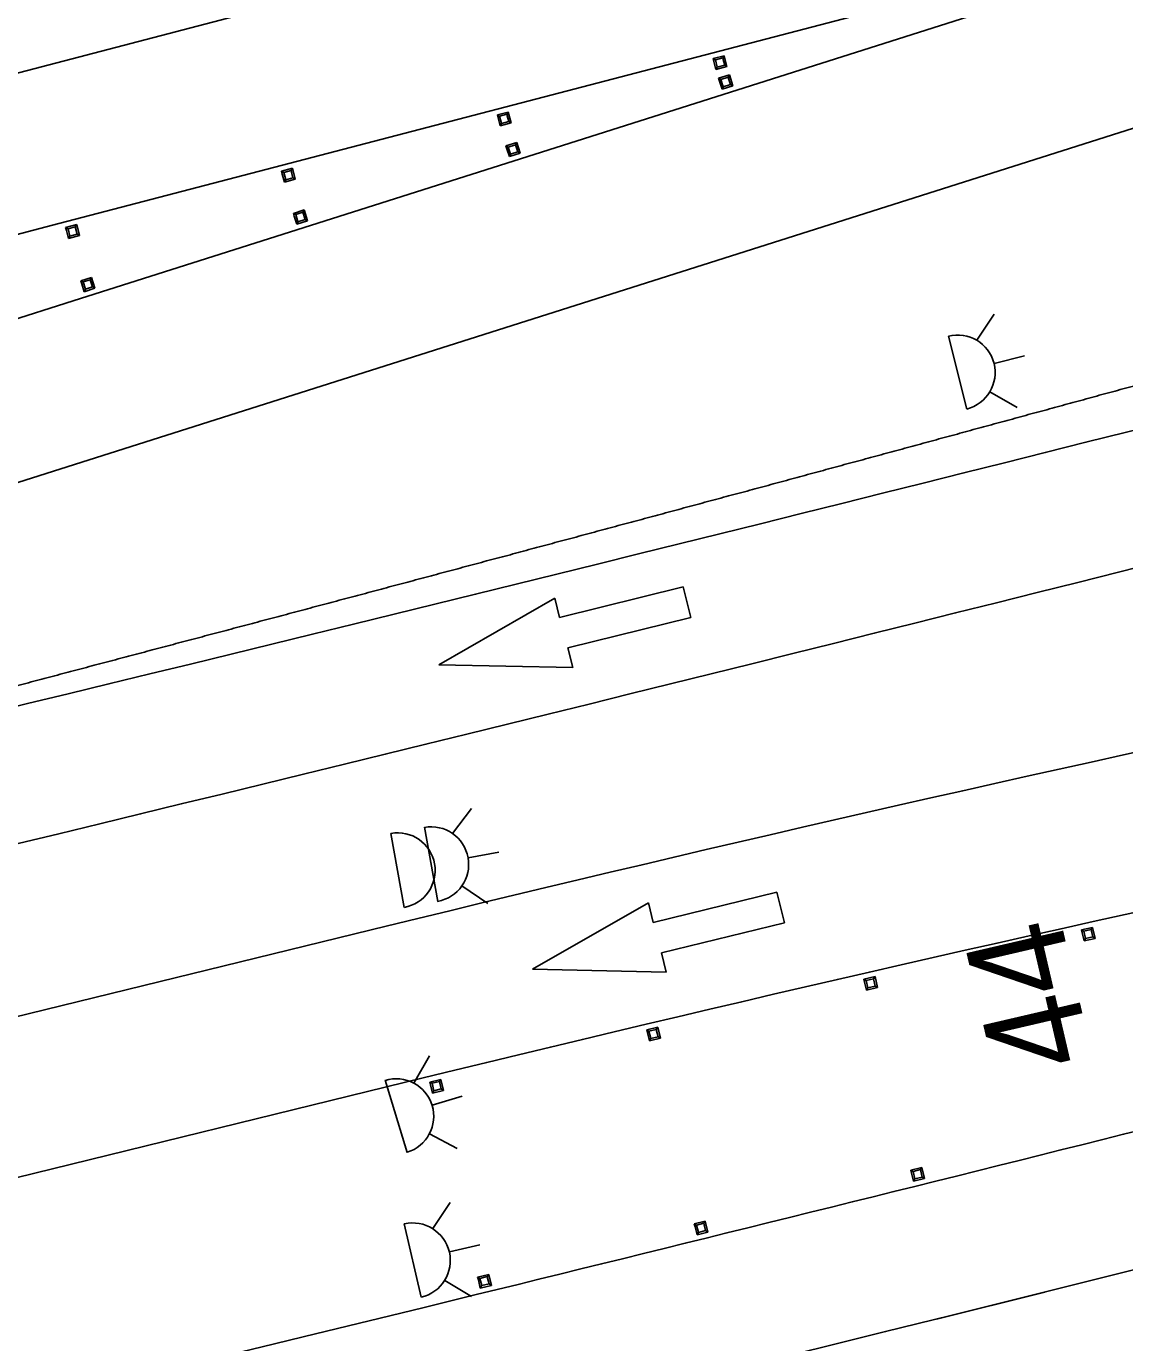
# Model space of a CAD drawing. Extents: x 2471014 to 2497726, y 6959577 to 6980268.
# Drawn here: x 2483642.2 to 2483740.7, y 6967742.6 to 6967860.6 of the extents above; entities that cross this region are included whole.
import ezdxf

# ---------------------------------------------------------------- set-up
doc = ezdxf.new("R2010")
doc.units = 0
for name, color, linetype in [('1', 7, 'Continuous'), ('13', 7, 'Continuous'), ('18', 7, 'Continuous'), ('23', 7, 'Continuous'), ('25', 7, 'Continuous'), ('5', 7, 'Continuous'), ('ALIGN_ML_IH35_NB_SB', 7, 'Continuous'), ('C-COMM-IDEN', 7, 'Continuous'), ('Level 30', 7, 'Continuous'), ('PMK_Del_D-SY_SZ_TYC_CTB', 7, 'Continuous'), ('PMK_Pav_Mark_Wht_Number', 7, 'Continuous'), ('S-BRDG-DECK', 7, 'Continuous'), ('V7_25', 7, 'Continuous')]:
    doc.layers.add(name, color=color, linetype=linetype)

msp = doc.modelspace()

# ---------------------------------------------------------------- linework, layer by layer
at = {"layer": '1'}
msp.add_line((2483733.49, 6967747.11), (2483723.78, 6967744.69), dxfattribs=at)
at = {"layer": '13'}
for p, q in [((2483621.13, 6967813.26), (2483744.66, 6967852.49)), ((2483645.1, 6967842.9), (2483440.68, 6967789.54)), ((2483529.53, 6967730.02), (2483677.76, 6967766.3))]:
    msp.add_line(p, q, dxfattribs=at)
msp.add_arc((2480976.22, 6978803.49), 11334, 283.600619, 284.818275, dxfattribs=at)
at = {"layer": '18'}
for p, q in [((2483589.04, 6967842.74), (2483885.7, 6967920.19)), ((2483453.46, 6967774.7), (2483647.04, 6967836.18)), ((2483526.2, 6967743.62), (2483674.43, 6967779.9))]:
    msp.add_line(p, q, dxfattribs=at)
for centre, radius, start, end in [((2484355.58, 6964997.05), 2865, 99.97631, 103.75383), ((2480975.49, 6978806.4), 11386, 280.569873, 283.75381)]:
    msp.add_arc(centre, radius, start, end, dxfattribs=at)
for points in [[(2483785.94, 6967840.59), (2483785, 6967840.33), (2483784.06, 6967840.07), (2483783.12, 6967839.81), (2483782.17, 6967839.55), (2483781.23, 6967839.29), (2483780.29, 6967839.03), (2483779.35, 6967838.77), (2483778.41, 6967838.51), (2483777.47, 6967838.25), (2483776.53, 6967837.98), (2483775.58, 6967837.72), (2483774.64, 6967837.46), (2483773.7, 6967837.2), (2483772.76, 6967836.94), (2483771.82, 6967836.68), (2483770.88, 6967836.42), (2483769.94, 6967836.16), (2483768.99, 6967835.9), (2483768.05, 6967835.64), (2483767.11, 6967835.38), (2483766.17, 6967835.12), (2483765.23, 6967834.86), (2483764.29, 6967834.6), (2483763.34, 6967834.35), (2483762.4, 6967834.09), (2483761.46, 6967833.83), (2483760.52, 6967833.57), (2483759.58, 6967833.31), (2483758.63, 6967833.05), (2483757.69, 6967832.79), (2483756.75, 6967832.53), (2483755.81, 6967832.27), (2483754.87, 6967832.01), (2483753.92, 6967831.75), (2483752.98, 6967831.5), (2483752.04, 6967831.24), (2483751.1, 6967830.98), (2483750.16, 6967830.72), (2483749.21, 6967830.46), (2483748.27, 6967830.2), (2483747.33, 6967829.95), (2483746.39, 6967829.69), (2483745.45, 6967829.43), (2483744.5, 6967829.17), (2483743.56, 6967828.91), (2483742.62, 6967828.66), (2483741.68, 6967828.4), (2483740.73, 6967828.14), (2483739.79, 6967827.88), (2483738.85, 6967827.63), (2483737.91, 6967827.37), (2483736.97, 6967827.11), (2483736.02, 6967826.86), (2483735.08, 6967826.6), (2483734.14, 6967826.34), (2483733.2, 6967826.08), (2483732.25, 6967825.83), (2483731.31, 6967825.57), (2483730.37, 6967825.31), (2483729.42, 6967825.06), (2483728.48, 6967824.8), (2483727.54, 6967824.55), (2483726.6, 6967824.29), (2483725.65, 6967824.03), (2483724.71, 6967823.78), (2483723.77, 6967823.52), (2483722.83, 6967823.26), (2483721.88, 6967823.01), (2483720.94, 6967822.75), (2483720, 6967822.5), (2483719.05, 6967822.24), (2483718.11, 6967821.99), (2483717.17, 6967821.73), (2483716.23, 6967821.47)], [(2483716.23, 6967821.47), (2483715.28, 6967821.22), (2483714.34, 6967820.96), (2483713.4, 6967820.71), (2483712.45, 6967820.45), (2483711.51, 6967820.2), (2483710.57, 6967819.94), (2483709.62, 6967819.69), (2483708.68, 6967819.43), (2483707.74, 6967819.18), (2483706.8, 6967818.92), (2483705.85, 6967818.67), (2483704.91, 6967818.42), (2483703.97, 6967818.16), (2483703.02, 6967817.91), (2483702.08, 6967817.65), (2483701.14, 6967817.4), (2483700.19, 6967817.14), (2483699.25, 6967816.89), (2483698.31, 6967816.64), (2483697.36, 6967816.38), (2483696.42, 6967816.13), (2483695.48, 6967815.88), (2483694.53, 6967815.62), (2483693.59, 6967815.37), (2483692.64, 6967815.12), (2483691.7, 6967814.86), (2483690.76, 6967814.61), (2483689.81, 6967814.36), (2483688.87, 6967814.1), (2483687.93, 6967813.85), (2483686.98, 6967813.6), (2483686.04, 6967813.34), (2483685.1, 6967813.09), (2483684.15, 6967812.84), (2483683.21, 6967812.59), (2483682.26, 6967812.33), (2483681.32, 6967812.08), (2483680.38, 6967811.83), (2483679.43, 6967811.58), (2483678.49, 6967811.32), (2483677.55, 6967811.07), (2483676.6, 6967810.82), (2483675.66, 6967810.57), (2483674.71, 6967810.32), (2483673.77, 6967810.06), (2483672.83, 6967809.81), (2483671.88, 6967809.56), (2483670.94, 6967809.31), (2483669.99, 6967809.06), (2483669.05, 6967808.81), (2483668.11, 6967808.56), (2483667.16, 6967808.3), (2483666.22, 6967808.05), (2483665.27, 6967807.8), (2483664.33, 6967807.55), (2483663.38, 6967807.3), (2483662.44, 6967807.05), (2483661.5, 6967806.8), (2483660.55, 6967806.55), (2483659.61, 6967806.3), (2483658.66, 6967806.05), (2483657.72, 6967805.8), (2483656.77, 6967805.55), (2483655.83, 6967805.3), (2483654.88, 6967805.05), (2483653.94, 6967804.8), (2483653, 6967804.55), (2483652.05, 6967804.3), (2483651.11, 6967804.05), (2483650.16, 6967803.8), (2483649.22, 6967803.55), (2483648.27, 6967803.3), (2483647.33, 6967803.05), (2483646.38, 6967802.8)], [(2483646.38, 6967802.8), (2483645.44, 6967802.55), (2483644.49, 6967802.3), (2483643.55, 6967802.05), (2483642.6, 6967801.8), (2483641.66, 6967801.55), (2483640.72, 6967801.3), (2483639.77, 6967801.05), (2483638.83, 6967800.81), (2483637.88, 6967800.56), (2483636.94, 6967800.31), (2483635.99, 6967800.06), (2483635.05, 6967799.81), (2483634.1, 6967799.56), (2483633.16, 6967799.31), (2483632.21, 6967799.07), (2483631.27, 6967798.82), (2483630.32, 6967798.57), (2483629.38, 6967798.32), (2483628.43, 6967798.07), (2483627.49, 6967797.83), (2483626.54, 6967797.58), (2483625.6, 6967797.33), (2483624.65, 6967797.08), (2483623.7, 6967796.84), (2483622.76, 6967796.59), (2483621.81, 6967796.34), (2483620.87, 6967796.09), (2483619.92, 6967795.85), (2483618.98, 6967795.6), (2483618.03, 6967795.35), (2483617.09, 6967795.11), (2483616.14, 6967794.86), (2483615.2, 6967794.61), (2483614.25, 6967794.37), (2483613.31, 6967794.12), (2483612.36, 6967793.87), (2483611.41, 6967793.63), (2483610.47, 6967793.38), (2483609.52, 6967793.13), (2483608.58, 6967792.89), (2483607.63, 6967792.64), (2483606.69, 6967792.4), (2483605.74, 6967792.15), (2483604.8, 6967791.9), (2483603.85, 6967791.66), (2483602.9, 6967791.41), (2483601.96, 6967791.17), (2483601.01, 6967790.92), (2483600.07, 6967790.68), (2483599.12, 6967790.43), (2483598.17, 6967790.19), (2483597.23, 6967789.94), (2483596.28, 6967789.69), (2483595.34, 6967789.45), (2483594.39, 6967789.2), (2483593.45, 6967788.96), (2483592.5, 6967788.72), (2483591.55, 6967788.47), (2483590.61, 6967788.23), (2483589.66, 6967787.98), (2483588.72, 6967787.74), (2483587.77, 6967787.49), (2483586.82, 6967787.25), (2483585.88, 6967787), (2483584.93, 6967786.76), (2483583.98, 6967786.52), (2483583.04, 6967786.27), (2483582.09, 6967786.03), (2483581.15, 6967785.78), (2483580.2, 6967785.54), (2483579.25, 6967785.3), (2483578.31, 6967785.05), (2483577.36, 6967784.81), (2483576.41, 6967784.57)]]:
    msp.add_spline(points, degree=3, dxfattribs=at)
at = {"layer": '23'}
for p, q in [((2483703.76, 6967857.7), (2483704.74, 6967857.95)), ((2483704.74, 6967857.95), (2483704.62, 6967857.76)), ((2483704.99, 6967856.97), (2483704.74, 6967857.95)), ((2483703.96, 6967857.59), (2483703.76, 6967857.7)), ((2483703.76, 6967857.7), (2483703.83, 6967857.44)), ((2483703.83, 6967857.44), (2483704.01, 6967856.72)), ((2483704.13, 6967856.93), (2483703.96, 6967857.59)), ((2483704.99, 6967856.97), (2483704.01, 6967856.72)), ((2483704.01, 6967856.72), (2483704.13, 6967856.93)), ((2483704.62, 6967857.76), (2483704.65, 6967857.62)), ((2483704.65, 6967857.62), (2483704.79, 6967857.1)), ((2483704.79, 6967857.1), (2483704.99, 6967856.97)), ((2483704.24, 6967855.92), (2483705.21, 6967856.23)), ((2483704.45, 6967855.82), (2483704.24, 6967855.92)), ((2483704.24, 6967855.92), (2483704.33, 6967855.66)), ((2483704.33, 6967855.66), (2483704.55, 6967854.95)), ((2483704.66, 6967855.17), (2483704.45, 6967855.82)), ((2483705.21, 6967856.23), (2483705.1, 6967856.02)), ((2483705.1, 6967856.02), (2483705.14, 6967855.89)), ((2483705.14, 6967855.89), (2483705.3, 6967855.38)), ((2483705.52, 6967855.26), (2483705.21, 6967856.23)), ((2483705.52, 6967855.26), (2483704.55, 6967854.95)), ((2483704.55, 6967854.95), (2483704.66, 6967855.17)), ((2483705.3, 6967855.38), (2483705.52, 6967855.26)), ((2483684.41, 6967852.65), (2483685.39, 6967852.9)), ((2483684.61, 6967852.53), (2483684.41, 6967852.65)), ((2483684.41, 6967852.65), (2483684.47, 6967852.39)), ((2483684.47, 6967852.39), (2483684.66, 6967851.66)), ((2483684.78, 6967851.88), (2483684.61, 6967852.53)), ((2483685.39, 6967852.9), (2483685.26, 6967852.7)), ((2483685.26, 6967852.7), (2483685.3, 6967852.57)), ((2483685.3, 6967852.57), (2483685.43, 6967852.05)), ((2483685.64, 6967851.92), (2483685.39, 6967852.9)), ((2483685.43, 6967852.05), (2483685.64, 6967851.92)), ((2483685.64, 6967851.92), (2483684.66, 6967851.66)), ((2483684.66, 6967851.66), (2483684.78, 6967851.88)), ((2483685.18, 6967849.86), (2483686.15, 6967850.17)), ((2483685.39, 6967849.76), (2483685.18, 6967849.86)), ((2483685.18, 6967849.86), (2483685.26, 6967849.61)), ((2483685.26, 6967849.61), (2483685.49, 6967848.9)), ((2483685.6, 6967849.12), (2483685.39, 6967849.76)), ((2483686.15, 6967850.17), (2483686.04, 6967849.97)), ((2483686.04, 6967849.97), (2483686.08, 6967849.83)), ((2483686.08, 6967849.83), (2483686.24, 6967849.32)), ((2483686.46, 6967849.2), (2483686.15, 6967850.17)), ((2483686.46, 6967849.2), (2483685.49, 6967848.9)), ((2483685.49, 6967848.9), (2483685.6, 6967849.12)), ((2483686.24, 6967849.32), (2483686.46, 6967849.2)), ((2483665.05, 6967847.59), (2483666.04, 6967847.85)), ((2483665.26, 6967847.48), (2483665.05, 6967847.59)), ((2483665.05, 6967847.59), (2483665.12, 6967847.33)), ((2483665.12, 6967847.33), (2483665.31, 6967846.61)), ((2483665.43, 6967846.83), (2483665.26, 6967847.48)), ((2483666.04, 6967847.85), (2483665.91, 6967847.65)), ((2483665.91, 6967847.65), (2483665.95, 6967847.52)), ((2483665.95, 6967847.52), (2483666.08, 6967847)), ((2483666.29, 6967846.87), (2483666.04, 6967847.85)), ((2483666.29, 6967846.87), (2483665.31, 6967846.61)), ((2483665.31, 6967846.61), (2483665.43, 6967846.83)), ((2483666.08, 6967847), (2483666.29, 6967846.87)), ((2483666.12, 6967843.81), (2483667.09, 6967844.12)), ((2483666.33, 6967843.71), (2483666.12, 6967843.81)), ((2483666.12, 6967843.81), (2483666.2, 6967843.55)), ((2483666.53, 6967843.06), (2483666.33, 6967843.71)), ((2483667.09, 6967844.12), (2483666.97, 6967843.91)), ((2483666.97, 6967843.91), (2483667.02, 6967843.78)), ((2483667.02, 6967843.78), (2483667.18, 6967843.27)), ((2483667.39, 6967843.15), (2483667.09, 6967844.12)), ((2483645.7, 6967842.54), (2483646.69, 6967842.8)), ((2483645.91, 6967842.43), (2483645.7, 6967842.54)), ((2483645.7, 6967842.54), (2483645.77, 6967842.28)), ((2483646.69, 6967842.8), (2483646.56, 6967842.6)), ((2483646.56, 6967842.6), (2483646.6, 6967842.46)), ((2483646.94, 6967841.82), (2483646.69, 6967842.8)), ((2483666.2, 6967843.55), (2483666.43, 6967842.84)), ((2483667.39, 6967843.15), (2483666.43, 6967842.84)), ((2483666.43, 6967842.84), (2483666.53, 6967843.06)), ((2483667.18, 6967843.27), (2483667.39, 6967843.15)), ((2483645.77, 6967842.28), (2483645.96, 6967841.56)), ((2483646.08, 6967841.77), (2483645.91, 6967842.43)), ((2483646.94, 6967841.82), (2483645.96, 6967841.56)), ((2483645.96, 6967841.56), (2483646.08, 6967841.77)), ((2483646.6, 6967842.46), (2483646.73, 6967841.95)), ((2483646.73, 6967841.95), (2483646.94, 6967841.82)), ((2483647.06, 6967837.76), (2483648.03, 6967838.06)), ((2483648.03, 6967838.06), (2483647.91, 6967837.86)), ((2483647.91, 6967837.86), (2483647.96, 6967837.73)), ((2483648.33, 6967837.1), (2483648.03, 6967838.06)), ((2483647.27, 6967837.66), (2483647.06, 6967837.76)), ((2483647.06, 6967837.76), (2483647.14, 6967837.5)), ((2483647.14, 6967837.5), (2483647.37, 6967836.79)), ((2483647.47, 6967837.01), (2483647.27, 6967837.66)), ((2483648.33, 6967837.1), (2483647.37, 6967836.79)), ((2483647.37, 6967836.79), (2483647.47, 6967837.01)), ((2483647.96, 6967837.73), (2483648.12, 6967837.22)), ((2483648.12, 6967837.22), (2483648.33, 6967837.1)), ((2483736.79, 6967779.57), (2483737.78, 6967779.79)), ((2483736.99, 6967779.45), (2483736.79, 6967779.57)), ((2483736.79, 6967779.57), (2483736.85, 6967779.31)), ((2483736.85, 6967779.31), (2483737.01, 6967778.58)), ((2483737.14, 6967778.79), (2483736.99, 6967779.45)), ((2483738, 6967778.8), (2483737.01, 6967778.58)), ((2483737.01, 6967778.58), (2483737.14, 6967778.79)), ((2483737.78, 6967779.79), (2483737.65, 6967779.6)), ((2483737.65, 6967779.6), (2483737.68, 6967779.46)), ((2483737.68, 6967779.46), (2483737.8, 6967778.94)), ((2483738, 6967778.8), (2483737.78, 6967779.79)), ((2483737.8, 6967778.94), (2483738, 6967778.8)), ((2483717.28, 6967775.16), (2483718.27, 6967775.39)), ((2483718.27, 6967775.39), (2483718.14, 6967775.2)), ((2483718.5, 6967774.4), (2483718.27, 6967775.39)), ((2483717.48, 6967775.04), (2483717.28, 6967775.16)), ((2483717.28, 6967775.16), (2483717.34, 6967774.9)), ((2483717.34, 6967774.9), (2483717.51, 6967774.17)), ((2483717.63, 6967774.38), (2483717.48, 6967775.04)), ((2483718.5, 6967774.4), (2483717.51, 6967774.17)), ((2483717.51, 6967774.17), (2483717.63, 6967774.38)), ((2483718.14, 6967775.2), (2483718.17, 6967775.06)), ((2483718.17, 6967775.06), (2483718.29, 6967774.54)), ((2483718.29, 6967774.54), (2483718.5, 6967774.4)), ((2483697.8, 6967770.61), (2483698.79, 6967770.85)), ((2483698, 6967770.5), (2483697.8, 6967770.61)), ((2483697.8, 6967770.61), (2483697.86, 6967770.35)), ((2483698.79, 6967770.85), (2483698.66, 6967770.65)), ((2483698.66, 6967770.65), (2483698.69, 6967770.52)), ((2483698.69, 6967770.52), (2483698.82, 6967770)), ((2483699.02, 6967769.86), (2483698.79, 6967770.85)), ((2483697.86, 6967770.35), (2483698.04, 6967769.63)), ((2483698.16, 6967769.84), (2483698, 6967770.5)), ((2483699.02, 6967769.86), (2483698.04, 6967769.63)), ((2483698.04, 6967769.63), (2483698.16, 6967769.84)), ((2483698.82, 6967770), (2483699.02, 6967769.86)), ((2483678.36, 6967765.93), (2483679.34, 6967766.17)), ((2483678.56, 6967765.82), (2483678.36, 6967765.93)), ((2483678.36, 6967765.93), (2483678.42, 6967765.67)), ((2483678.72, 6967765.16), (2483678.56, 6967765.82)), ((2483679.34, 6967766.17), (2483679.21, 6967765.98)), ((2483679.21, 6967765.98), (2483679.25, 6967765.84)), ((2483679.25, 6967765.84), (2483679.37, 6967765.32)), ((2483679.58, 6967765.19), (2483679.34, 6967766.17)), ((2483678.42, 6967765.67), (2483678.6, 6967764.95)), ((2483679.58, 6967765.19), (2483678.6, 6967764.95)), ((2483678.6, 6967764.95), (2483678.72, 6967765.16)), ((2483679.37, 6967765.32), (2483679.58, 6967765.19)), ((2483721.48, 6967758.03), (2483722.46, 6967758.27)), ((2483721.68, 6967757.91), (2483721.48, 6967758.03)), ((2483721.48, 6967758.03), (2483721.54, 6967757.77)), ((2483721.54, 6967757.77), (2483721.72, 6967757.04)), ((2483721.84, 6967757.26), (2483721.68, 6967757.91)), ((2483722.46, 6967758.27), (2483722.34, 6967758.08)), ((2483722.34, 6967758.08), (2483722.37, 6967757.94)), ((2483722.37, 6967757.94), (2483722.5, 6967757.42)), ((2483722.71, 6967757.29), (2483722.46, 6967758.27)), ((2483722.71, 6967757.29), (2483721.72, 6967757.04)), ((2483721.72, 6967757.04), (2483721.84, 6967757.26)), ((2483722.5, 6967757.42), (2483722.71, 6967757.29)), ((2483702.06, 6967753.22), (2483703.05, 6967753.46)), ((2483702.26, 6967753.11), (2483702.06, 6967753.22)), ((2483702.06, 6967753.22), (2483702.13, 6967752.96)), ((2483702.13, 6967752.96), (2483702.31, 6967752.24)), ((2483702.43, 6967752.45), (2483702.26, 6967753.11)), ((2483703.05, 6967753.46), (2483702.92, 6967753.27)), ((2483702.92, 6967753.27), (2483702.96, 6967753.13)), ((2483702.96, 6967753.13), (2483703.08, 6967752.61)), ((2483703.29, 6967752.48), (2483703.05, 6967753.46)), ((2483703.29, 6967752.48), (2483702.31, 6967752.24)), ((2483702.31, 6967752.24), (2483702.43, 6967752.45)), ((2483703.08, 6967752.61), (2483703.29, 6967752.48)), ((2483682.64, 6967748.45), (2483683.63, 6967748.69)), ((2483682.84, 6967748.33), (2483682.64, 6967748.45)), ((2483682.64, 6967748.45), (2483682.71, 6967748.19)), ((2483682.71, 6967748.19), (2483682.88, 6967747.46)), ((2483683, 6967747.68), (2483682.84, 6967748.33)), ((2483683.63, 6967748.69), (2483683.5, 6967748.49)), ((2483683.5, 6967748.49), (2483683.53, 6967748.36)), ((2483683.53, 6967748.36), (2483683.66, 6967747.84)), ((2483683.87, 6967747.7), (2483683.63, 6967748.69)), ((2483683.87, 6967747.7), (2483682.88, 6967747.46)), ((2483682.88, 6967747.46), (2483683, 6967747.68)), ((2483683.66, 6967747.84), (2483683.87, 6967747.7))]:
    msp.add_line(p, q, dxfattribs=at)
for points in [[(2483703.96, 6967857.59), (2483704.62, 6967857.76), (2483704.79, 6967857.1), (2483704.13, 6967856.93)], [(2483704.45, 6967855.82), (2483705.1, 6967856.02), (2483705.3, 6967855.38), (2483704.66, 6967855.17)], [(2483684.61, 6967852.53), (2483685.26, 6967852.7), (2483685.43, 6967852.05), (2483684.78, 6967851.88)], [(2483685.39, 6967849.76), (2483686.04, 6967849.97), (2483686.24, 6967849.32), (2483685.6, 6967849.12)], [(2483665.26, 6967847.48), (2483665.91, 6967847.65), (2483666.08, 6967847), (2483665.43, 6967846.83)], [(2483666.33, 6967843.71), (2483666.97, 6967843.91), (2483667.18, 6967843.27), (2483666.53, 6967843.06)], [(2483645.91, 6967842.43), (2483646.56, 6967842.6), (2483646.73, 6967841.95), (2483646.08, 6967841.77)], [(2483647.27, 6967837.66), (2483647.91, 6967837.86), (2483648.12, 6967837.22), (2483647.47, 6967837.01)], [(2483736.99, 6967779.45), (2483737.65, 6967779.6), (2483737.8, 6967778.94), (2483737.14, 6967778.79)], [(2483717.48, 6967775.04), (2483718.14, 6967775.2), (2483718.29, 6967774.54), (2483717.63, 6967774.38)], [(2483698, 6967770.5), (2483698.66, 6967770.65), (2483698.82, 6967770), (2483698.16, 6967769.84)], [(2483678.56, 6967765.82), (2483679.21, 6967765.98), (2483679.37, 6967765.32), (2483678.72, 6967765.16)], [(2483721.68, 6967757.91), (2483722.34, 6967758.08), (2483722.5, 6967757.42), (2483721.84, 6967757.26)], [(2483702.26, 6967753.11), (2483702.92, 6967753.27), (2483703.08, 6967752.61), (2483702.43, 6967752.45)], [(2483682.84, 6967748.33), (2483683.5, 6967748.49), (2483683.66, 6967747.84), (2483683, 6967747.68)]]:
    msp.add_lwpolyline(points, close=True, dxfattribs=at)
at = {"layer": '25'}
for p, q in [((2483645.1, 6967842.9), (2483780.79, 6967878.33)), ((2483647.04, 6967836.18), (2483740.43, 6967865.84))]:
    msp.add_line(p, q, dxfattribs=at)
for centre, radius, start, end in [((2484355.58, 6964997.05), 2851, 99.97631, 103.75383), ((2480975.49, 6978806.4), 11386, 283.75381, 284.37496)]:
    msp.add_arc(centre, radius, start, end, dxfattribs=at)
at = {"layer": '5'}
msp.add_arc((2479474.04, 6969335.88), 8460, 6.37617, 6.37617, dxfattribs=at)
at = {"layer": 'ALIGN_ML_IH35_NB_SB'}
for p, q in [((2483689.99, 6967807.57), (2483701.08, 6967810.32)), ((2483701.08, 6967810.32), (2483701.76, 6967807.58)), ((2483679.17, 6967803.35), (2483689.56, 6967809.32)), ((2483689.56, 6967809.32), (2483689.99, 6967807.57)), ((2483701.76, 6967807.58), (2483690.73, 6967804.85)), ((2483690.73, 6967804.85), (2483691.16, 6967803.1)), ((2483691.16, 6967803.1), (2483679.17, 6967803.35)), ((2483698.38, 6967780.24), (2483709.48, 6967782.96)), ((2483709.48, 6967782.96), (2483710.15, 6967780.22)), ((2483687.55, 6967776.05), (2483697.95, 6967781.99)), ((2483697.95, 6967781.99), (2483698.38, 6967780.24)), ((2483710.15, 6967780.22), (2483699.11, 6967777.52)), ((2483699.11, 6967777.52), (2483699.54, 6967775.77)), ((2483699.54, 6967775.77), (2483687.55, 6967776.05))]:
    msp.add_line(p, q, dxfattribs=at)
at = {"layer": 'C-COMM-IDEN'}
for p, q in [((2483680.39, 6967788.22), (2483682.09, 6967790.46)), ((2483676.05, 6967781.59), (2483674.86, 6967788.23)), ((2483674.86, 6967788.23), (2483676.05, 6967781.59)), ((2483677.87, 6967788.77), (2483679.06, 6967782.13)), ((2483681.79, 6967786.04), (2483684.55, 6967786.54)), ((2483681.23, 6967783.52), (2483683.56, 6967781.94))]:
    msp.add_line(p, q, dxfattribs=at)
for centre in [(2483675.46, 6967784.91), (2483678.46, 6967785.45)]:
    msp.add_arc(centre, 3.37, 280.1538, 100.1538, dxfattribs=at)
at = {"layer": 'Level 30'}
for p, q in [((2483727.4, 6967832.44), (2483728.94, 6967834.79)), ((2483726.5, 6967826.27), (2483724.85, 6967832.81)), ((2483728.95, 6967830.36), (2483731.67, 6967831.05)), ((2483728.57, 6967827.81), (2483731.01, 6967826.4)), ((2483678.61, 6967752.8), (2483680.18, 6967755.13)), ((2483677.59, 6967746.64), (2483676.06, 6967753.22)), ((2483680.11, 6967750.7), (2483682.85, 6967751.34)), ((2483679.69, 6967748.15), (2483682.1, 6967746.7))]:
    msp.add_line(p, q, dxfattribs=at)
for centre, start, end in [((2483725.67, 6967829.54), 284.1567, 104.1567), ((2483676.82, 6967749.93), 283.1168, 103.1168)]:
    msp.add_arc(centre, 3.37, start, end, dxfattribs=at)
at = {"layer": 'PMK_Del_D-SY_SZ_TYC_CTB'}
for p, q in [((2483676.91, 6967765.84), (2483678.33, 6967768.27)), ((2483674.34, 6967766.09), (2483676.32, 6967759.63)), ((2483678.56, 6967763.85), (2483681.25, 6967764.67)), ((2483678.31, 6967761.28), (2483680.81, 6967759.99))]:
    msp.add_line(p, q, dxfattribs=at)
msp.add_arc((2483675.33, 6967762.86), 3.37, 287.0006, 107.0006, dxfattribs=at)
at = {"layer": 'S-BRDG-DECK'}
msp.add_arc((2480976.22, 6978803.49), 11322, 283.600619, 284.818275, dxfattribs=at)
at = {"layer": 'V7_25'}
for radius in [11398, 11398, 11410, 11410]:
    msp.add_arc((2480975.49, 6978806.4), radius, 280.569873, 284.37496, dxfattribs=at)

# ---------------------------------------------------------------- texts
at = {"layer": 'PMK_Pav_Mark_Wht_Number'}
msp.add_text('44', height=8.9, rotation=103.1016, dxfattribs=at).set_placement((2483737.8, 6967768.08))

doc.saveas('drawing.dxf')
